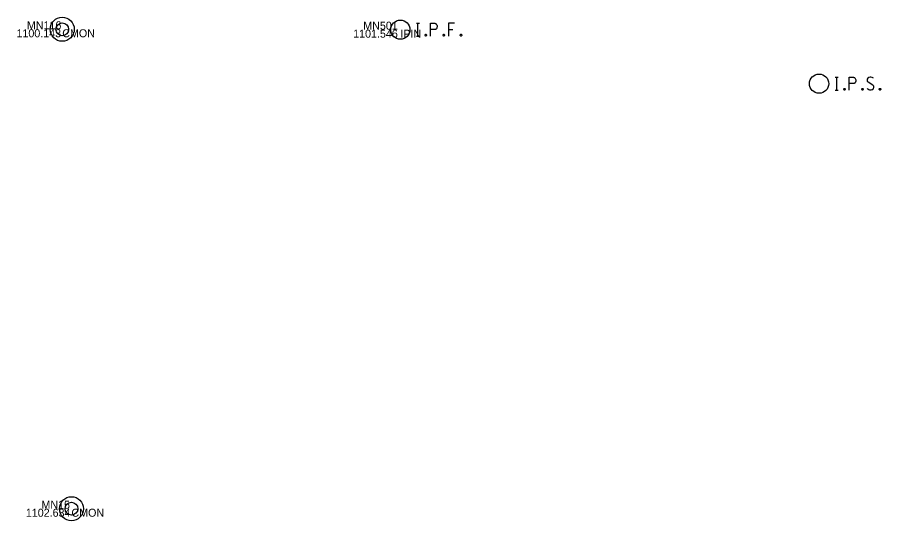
# Model space of a CAD drawing. Extents: x 2402028 to 2407435, y 498611 to 499105.
# Drawn here: x 2402028.5 to 2402136.4, y 498614.1 to 498676.9 of the extents above; entities that cross this region are included whole.
import ezdxf

# ---------------------------------------------------------------- set-up
doc = ezdxf.new("R2010")
doc.units = 0
for name, color, linetype in [('_CIVIL_CONSTRUCTION', 7, 'Continuous'), ('RW_X_CL', 7, 'Continuous'), ('RW_X_CL_100_Bearings', 7, 'Continuous'), ('RW_X_CL_100_Cardinal_Points', 7, 'Continuous'), ('RW_X_CL_100_Stations', 7, 'Continuous')]:
    doc.layers.add(name, color=color, linetype=linetype)

msp = doc.modelspace()

# ---------------------------------------------------------------- linework, layer by layer
at = {"layer": 'RW_X_CL'}
for points in [[(2402130.73, 498669.44), (2402131.08, 498669.44)], [(2402130.91, 498667.84), (2402130.91, 498669.44)], [(2402132.47, 498667.84), (2402132.47, 498669.44), (2402133, 498669.44), (2402133.05, 498669.42), (2402133.13, 498669.4), (2402133.17, 498669.37), (2402133.2, 498669.35), (2402133.24, 498669.29), (2402133.28, 498669.22), (2402133.3, 498669.12), (2402133.3, 498668.97), (2402133.29, 498668.92), (2402133.26, 498668.85), (2402133.22, 498668.76), (2402133.18, 498668.72), (2402133.14, 498668.69), (2402133.09, 498668.67), (2402133, 498668.66), (2402132.47, 498668.66)], [(2402135.48, 498669.32), (2402135.46, 498669.35), (2402135.42, 498669.37), (2402135.33, 498669.41), (2402135.2, 498669.44), (2402135.12, 498669.44), (2402135.08, 498669.44), (2402134.94, 498669.4), (2402134.82, 498669.32), (2402134.74, 498669.22), (2402134.72, 498669.12), (2402134.72, 498669.05), (2402134.74, 498668.95), (2402134.83, 498668.86), (2402135.44, 498668.48), (2402135.49, 498668.43), (2402135.51, 498668.38), (2402135.53, 498668.3), (2402135.53, 498668.23), (2402135.52, 498668.15), (2402135.51, 498668.1), (2402135.49, 498668.04), (2402135.47, 498667.99), (2402135.45, 498667.95), (2402135.41, 498667.91), (2402135.38, 498667.89), (2402135.34, 498667.86), (2402135.3, 498667.85), (2402135.2, 498667.84), (2402135.05, 498667.84), (2402134.95, 498667.86), (2402134.81, 498667.95), (2402134.72, 498668.03)], [(2402130.73, 498667.84), (2402131.08, 498667.84)], [(2402131.86, 498668.05), (2402131.92, 498668.05), (2402131.95, 498668.03), (2402131.99, 498667.98), (2402131.99, 498667.91), (2402131.95, 498667.86), (2402131.92, 498667.84), (2402131.86, 498667.84), (2402131.83, 498667.86), (2402131.8, 498667.91), (2402131.8, 498667.98), (2402131.83, 498668.03), (2402131.86, 498668.05)], [(2402134.11, 498668.05), (2402134.17, 498668.05), (2402134.2, 498668.03), (2402134.23, 498667.98), (2402134.23, 498667.91), (2402134.2, 498667.86), (2402134.17, 498667.84), (2402134.11, 498667.84), (2402134.08, 498667.86), (2402134.05, 498667.91), (2402134.05, 498667.98), (2402134.08, 498668.03), (2402134.11, 498668.05)], [(2402136.3, 498668.05), (2402136.35, 498668.05), (2402136.38, 498668.03), (2402136.42, 498667.98), (2402136.42, 498667.91), (2402136.38, 498667.86), (2402136.35, 498667.84), (2402136.3, 498667.84), (2402136.26, 498667.86), (2402136.23, 498667.91), (2402136.23, 498667.98), (2402136.26, 498668.03), (2402136.3, 498668.05)]]:
    msp.add_lwpolyline(points, dxfattribs=at)
msp.add_circle((2402128.71, 498668.64), 1.2, dxfattribs=at)
at = {"layer": 'RW_X_CL_100_Stations'}
for points in [[(2402078.39, 498676.18), (2402078.75, 498676.18)], [(2402078.57, 498674.58), (2402078.57, 498676.18)], [(2402080.14, 498674.58), (2402080.14, 498676.18), (2402080.67, 498676.18), (2402080.72, 498676.17), (2402080.8, 498676.14), (2402080.83, 498676.12), (2402080.86, 498676.09), (2402080.91, 498676.03), (2402080.94, 498675.97), (2402080.96, 498675.87), (2402080.96, 498675.72), (2402080.95, 498675.66), (2402080.93, 498675.59), (2402080.89, 498675.5), (2402080.84, 498675.46), (2402080.81, 498675.44), (2402080.75, 498675.41), (2402080.67, 498675.4), (2402080.14, 498675.4)], [(2402083.15, 498676.18), (2402082.38, 498676.18), (2402082.38, 498674.58)], [(2402078.39, 498674.58), (2402078.75, 498674.58)], [(2402079.53, 498674.8), (2402079.58, 498674.8), (2402079.62, 498674.77), (2402079.65, 498674.72), (2402079.65, 498674.66), (2402079.62, 498674.61), (2402079.58, 498674.58), (2402079.53, 498674.58), (2402079.5, 498674.61), (2402079.46, 498674.66), (2402079.46, 498674.72), (2402079.5, 498674.77), (2402079.53, 498674.8)], [(2402081.78, 498674.8), (2402081.83, 498674.8), (2402081.87, 498674.77), (2402081.9, 498674.72), (2402081.9, 498674.66), (2402081.87, 498674.61), (2402081.83, 498674.58), (2402081.78, 498674.58), (2402081.75, 498674.61), (2402081.71, 498674.66), (2402081.71, 498674.72), (2402081.75, 498674.77), (2402081.78, 498674.8)], [(2402082.38, 498675.4), (2402082.92, 498675.4)], [(2402083.93, 498674.8), (2402083.98, 498674.8), (2402084.02, 498674.77), (2402084.05, 498674.72), (2402084.05, 498674.66), (2402084.02, 498674.61), (2402083.98, 498674.58), (2402083.93, 498674.58), (2402083.89, 498674.61), (2402083.86, 498674.66), (2402083.86, 498674.72), (2402083.89, 498674.77), (2402083.93, 498674.8)]]:
    msp.add_lwpolyline(points, dxfattribs=at)
for centre, radius in [((2402034.12, 498675.43), 1.5), ((2402034.12, 498675.43), 0.8), ((2402076.38, 498675.38), 1.2), ((2402035.27, 498615.58), 1.5), ((2402035.27, 498615.58), 0.8)]:
    msp.add_circle(centre, radius, dxfattribs=at)

# ---------------------------------------------------------------- texts
at = {"layer": '_CIVIL_CONSTRUCTION'}
for s, p in [('MN116', (2402029.7, 498675.43)), ('MN501', (2402071.74, 498675.38)), ('MN15', (2402031.52, 498615.58))]:
    msp.add_text(s, height=1, dxfattribs=at).set_placement(p)
at = {"layer": 'RW_X_CL_100_Bearings'}
for s, p in [('1100.143', (2402028.4, 498674.43)), ('1101.546', (2402070.48, 498674.38)), ('1102.634', (2402029.57, 498614.58))]:
    msp.add_text(s, height=1, dxfattribs=at).set_placement(p)
at = {"layer": 'RW_X_CL_100_Cardinal_Points'}
for s, p in [('CMON', (2402034.12, 498674.43)), ('IPIN', (2402076.38, 498674.38)), ('CMON', (2402035.27, 498614.58))]:
    msp.add_text(s, height=1, dxfattribs=at).set_placement(p)

doc.saveas('drawing.dxf')
